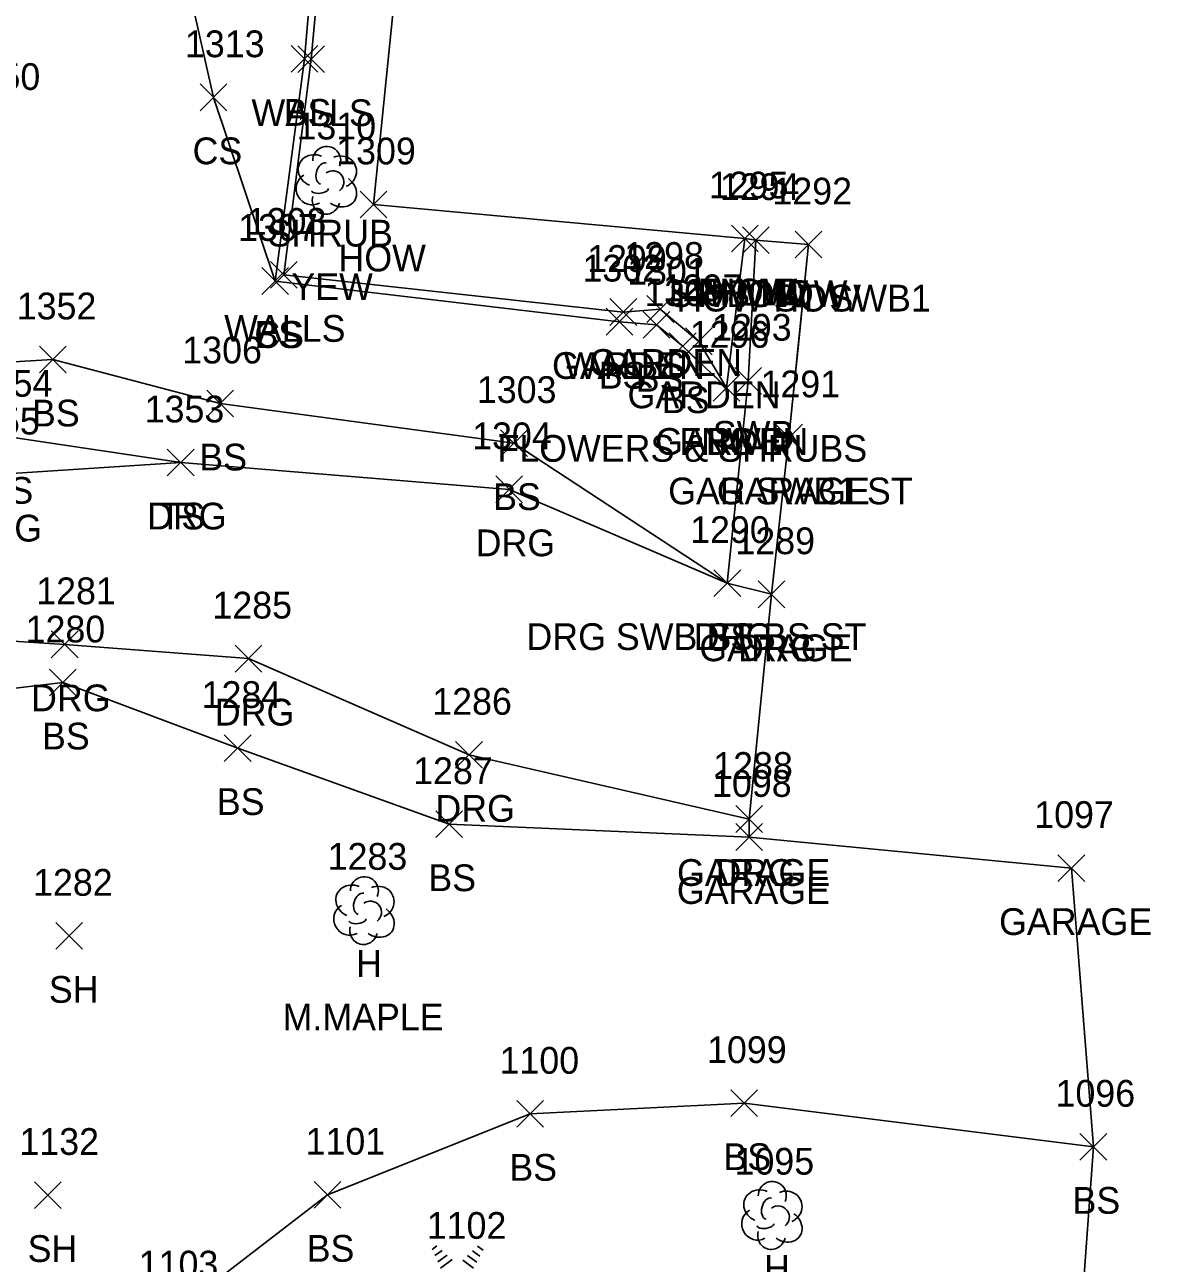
# Model space of a CAD drawing. Extents: x 1459992 to 1461532, y 647785 to 648535.
# Drawn here: x 1461426.2 to 1461510.8, y 648040.8 to 648133.4 of the extents above; entities that cross this region are included whole.
import ezdxf

# ---------------------------------------------------------------- set-up
doc = ezdxf.new("R2010")
doc.units = 0
for name, color, linetype in [('L_A', 7, 'Continuous'), ('L_C', 7, 'Continuous'), ('L_I', 7, 'Continuous'), ('L_TIC', 7, 'Continuous'), ('LAPB', 7, 'Continuous'), ('LBC', 7, 'Continuous'), ('LELB', 7, 'Continuous'), ('LFNC', 7, 'Continuous'), ('LSH', 7, 'Continuous'), ('LSOGP', 7, 'Continuous'), ('LTC', 7, 'Continuous'), ('LTD', 7, 'Continuous'), ('LWS', 7, 'Continuous'), ('R_A', 7, 'Continuous'), ('R_I', 7, 'Continuous'), ('R_TIC', 7, 'Continuous'), ('RDG', 7, 'Continuous'), ('RSW', 7, 'Continuous')]:
    doc.layers.add(name, color=color, linetype=linetype)

msp = doc.modelspace()

# ---------------------------------------------------------------- linework, layer by layer
at = {"layer": 'L_TIC'}
for points in [[(1461446.088, 648129.848), (1461448.088, 648131.848)], [(1461448.088, 648129.848), (1461446.088, 648131.848)], [(1461446.586, 648129.826), (1461448.586, 648131.826)], [(1461448.586, 648129.826), (1461446.586, 648131.826)], [(1461439.283, 648126.978), (1461441.283, 648128.978)], [(1461441.283, 648126.978), (1461439.283, 648128.978)], [(1461451.246, 648118.97), (1461453.246, 648120.97)], [(1461453.246, 648118.97), (1461451.246, 648120.97)], [(1461479.013, 648116.425), (1461481.013, 648118.425)], [(1461481.013, 648116.425), (1461479.013, 648118.425)], [(1461479.013, 648116.425), (1461481.013, 648118.425)], [(1461481.013, 648116.425), (1461479.013, 648118.425)], [(1461479.834, 648116.302), (1461481.834, 648118.302)], [(1461481.834, 648116.302), (1461479.834, 648118.302)], [(1461483.766, 648115.971), (1461485.766, 648117.971)], [(1461485.766, 648115.971), (1461483.766, 648117.971)], [(1461443.9, 648113.251), (1461445.9, 648115.251)], [(1461445.9, 648113.251), (1461443.9, 648115.251)], [(1461443.9, 648113.251), (1461445.9, 648115.251)], [(1461445.9, 648113.251), (1461443.9, 648115.251)], [(1461444.548, 648113.706), (1461446.548, 648115.706)], [(1461446.548, 648113.706), (1461444.548, 648115.706)], [(1461469.924, 648110.932), (1461471.924, 648112.932)], [(1461471.924, 648110.932), (1461469.924, 648112.932)], [(1461469.924, 648110.932), (1461471.924, 648112.932)], [(1461471.924, 648110.932), (1461469.924, 648112.932)], [(1461472.691, 648111.158), (1461474.691, 648113.158)], [(1461474.691, 648111.158), (1461472.691, 648113.158)], [(1461469.642, 648110.211), (1461471.642, 648112.211)], [(1461471.642, 648110.211), (1461469.642, 648112.211)], [(1461472.414, 648109.979), (1461474.414, 648111.979)], [(1461474.414, 648109.979), (1461472.414, 648111.979)], [(1461475.57, 648108.742), (1461477.57, 648110.742)], [(1461477.57, 648108.742), (1461475.57, 648110.742)], [(1461474.363, 648108.376), (1461476.363, 648110.376)], [(1461476.363, 648108.376), (1461474.363, 648110.376)], [(1461427.276, 648107.381), (1461429.276, 648109.381)], [(1461429.276, 648107.381), (1461427.276, 648109.381)], [(1461477.642, 648105.259), (1461479.642, 648107.259)], [(1461479.642, 648105.259), (1461477.642, 648107.259)], [(1461477.642, 648105.259), (1461479.642, 648107.259)], [(1461479.642, 648105.259), (1461477.642, 648107.259)], [(1461477.642, 648105.259), (1461479.642, 648107.259)], [(1461479.642, 648105.259), (1461477.642, 648107.259)], [(1461439.785, 648104.09), (1461441.785, 648106.09)], [(1461441.785, 648104.09), (1461439.785, 648106.09)], [(1461461.751, 648101.134), (1461463.751, 648103.134)], [(1461463.751, 648101.134), (1461461.751, 648103.134)], [(1461482.309, 648101.559), (1461484.309, 648103.559)], [(1461484.309, 648101.559), (1461482.309, 648103.559)], [(1461436.839, 648099.682), (1461438.839, 648101.682)], [(1461438.839, 648099.682), (1461436.839, 648101.682)], [(1461477.701, 648090.669), (1461479.701, 648092.669)], [(1461479.701, 648090.669), (1461477.701, 648092.669)], [(1461481.007, 648089.834), (1461483.007, 648091.834)], [(1461483.007, 648089.834), (1461481.007, 648091.834)], [(1461428.026, 648083.238), (1461430.026, 648085.238)], [(1461430.026, 648083.238), (1461428.026, 648085.238)], [(1461441.097, 648078.34), (1461443.097, 648080.34)], [(1461443.097, 648078.34), (1461441.097, 648080.34)], [(1461456.906, 648072.647), (1461458.906, 648074.647)], [(1461458.906, 648072.647), (1461456.906, 648074.647)], [(1461479.341, 648073.039), (1461481.341, 648075.039)], [(1461481.341, 648073.039), (1461479.341, 648075.039)], [(1461479.33, 648071.695), (1461481.33, 648073.695)], [(1461481.33, 648071.695), (1461479.33, 648073.695)], [(1461503.417, 648069.371), (1461505.417, 648071.371)], [(1461505.417, 648069.371), (1461503.417, 648071.371)], [(1461428.496, 648064.303), (1461430.496, 648066.303)], [(1461430.496, 648064.303), (1461428.496, 648066.303)], [(1461478.966, 648051.799), (1461480.966, 648053.799)], [(1461480.966, 648051.799), (1461478.966, 648053.799)], [(1461462.964, 648051.002), (1461464.964, 648053.002)], [(1461464.964, 648051.002), (1461462.964, 648053.002)], [(1461505.064, 648048.536), (1461507.064, 648050.536)], [(1461507.064, 648048.536), (1461505.064, 648050.536)], [(1461426.909, 648044.934), (1461428.909, 648046.934)], [(1461428.909, 648044.934), (1461426.909, 648046.934)], [(1461447.813, 648044.95), (1461449.813, 648046.95)], [(1461449.813, 648044.95), (1461447.813, 648046.95)]]:
    msp.add_lwpolyline(points, dxfattribs=at)
at = {"layer": 'LAPB'}
msp.add_lwpolyline([(1461478.642, 648106.259), (1461476.57, 648109.742), (1461473.691, 648112.158), (1461470.924, 648111.932)], dxfattribs=at)
at = {"layer": 'LBC'}
for points in [[(1461484.766, 648116.971), (1461480.834, 648117.302), (1461480.013, 648117.425), (1461452.246, 648119.97), (1461454.719, 648144.346), (1461455.253, 648148.958), (1461456.188, 648156.006), (1461467.518, 648153.848), (1461468.549, 648154.495), (1461472.343, 648154.285), (1461472.694, 648154.145), (1461482.334, 648153.047), (1461488.134, 648152.667), (1461488.857, 648152.617), (1461489.981, 648152.534), (1461490.817, 648159.203), (1461493.888, 648169.678), (1461510.763, 648168.099)], [(1461504.417, 648070.371), (1461480.33, 648072.695), (1461480.341, 648074.039), (1461482.007, 648090.834), (1461483.309, 648102.559)]]:
    msp.add_lwpolyline(points, dxfattribs=at)
at = {"layer": 'LELB'}
for points in [[(1461437.839, 648100.682), (1461424.99, 648102.601), (1461410.253, 648104.75), (1461403.249, 648108.099), (1461397.824, 648111.829), (1461393.938, 648122.147), (1461389.604, 648129.591), (1461386.85, 648142.876), (1461378.611, 648152.668), (1461368.623, 648163.532), (1461366.902, 648163.443), (1461362.607, 648163.899), (1461362.17, 648163.299)], [(1461478.642, 648106.259), (1461475.363, 648109.376), (1461473.414, 648110.979), (1461470.642, 648111.211), (1461444.9, 648114.251), (1461447.088, 648130.848), (1461448.323, 648145.003)], [(1461444.9, 648114.251), (1461440.283, 648127.978), (1461437.277, 648141.38), (1461441.027, 648143.03)], [(1461478.701, 648091.669), (1461462.751, 648102.134), (1461440.785, 648105.09), (1461428.276, 648108.381), (1461412.42, 648107.446), (1461407.924, 648110.162)], [(1461409.621, 648042.868), (1461407.442, 648074.421), (1461411.254, 648075.168), (1461411.242, 648082.118), (1461429.026, 648084.238), (1461442.097, 648079.34), (1461457.906, 648073.647)], [(1461457.906, 648073.647), (1461480.33, 648072.695)], [(1461506.064, 648049.536), (1461479.966, 648052.799), (1461463.964, 648052.002), (1461448.813, 648045.95), (1461436.904, 648036.773), (1461445.761, 648020.391), (1461448.916, 648009.123), (1461443.789, 647990.405)]]:
    msp.add_lwpolyline(points, dxfattribs=at)
at = {"layer": 'LFNC'}
msp.add_lwpolyline([(1461480.013, 648117.425), (1461478.642, 648106.259)], dxfattribs=at)
at = {"layer": 'LSH'}
msp.add_line((1461448.709, 648121.828), (1461448.709, 648121.828), dxfattribs=at)
msp.add_line((1461448.709, 648121.828), (1461448.709, 648121.828), dxfattribs=at)
msp.add_arc((1461448.756, 648123.262), 1.047, 335.52715, 180.95627, dxfattribs=at)
for centre, major_axis, ratio, start_param, end_param in [((1461447.917, 648122.495), (1.21, -0.512), 0.895232, 1.570796, 4.712389), ((1461449.751, 648122.412), (-1.141, -0.483), 0.949671, 1.570796, 4.712389), ((1461448.501, 648122.286), (-0.208, -0.792), 0.645439, 3.141593, 6.283185), ((1461449.209, 648121.662), (-0.5, 0.667), 0.989748, 3.141593, 6.283185), ((1461447.626, 648121.12), (0.584, -1.042), 0.959034, 3.141593, 6.283185), ((1461449.709, 648120.995), (-1.09, 0.792), 0.841452, 1.570796, 4.712389), ((1461448.251, 648121.078), (-0.625, -0.083), 0.423636, 0, 3.141593), ((1461448.709, 648120.328), (0.265, 1.061), 0.942809, 1.570796, 4.712389)]:
    msp.add_ellipse(centre, major_axis=major_axis, ratio=ratio, start_param=start_param, end_param=end_param, dxfattribs=at)
at = {"layer": 'LSOGP'}
msp.add_lwpolyline([(1461503.631, 648016.057), (1461506.064, 648049.536), (1461504.417, 648070.371), (1461480.33, 648072.695), (1461480.341, 648074.039), (1461482.007, 648090.834), (1461483.309, 648102.559), (1461484.038, 648109.765), (1461484.766, 648116.971), (1461480.834, 648117.302), (1461480.013, 648117.425), (1461452.246, 648119.97), (1461454.719, 648144.346)], dxfattribs=at)
at = {"layer": 'LTC'}
for p, q in [((1461456.634, 648041.87), (1461456.988, 648042.128)), ((1461460.032, 648042.111), (1461460.451, 648041.806)), ((1461456.843, 648041.405), (1461457.372, 648041.789)), ((1461457.053, 648040.939), (1461457.757, 648041.45)), ((1461457.262, 648040.473), (1461458.141, 648041.111)), ((1461458.919, 648041.066), (1461459.728, 648040.477)), ((1461459.29, 648041.414), (1461459.969, 648040.92)), ((1461459.661, 648041.762), (1461460.21, 648041.363))]:
    msp.add_line(p, q, dxfattribs=at)
at = {"layer": 'LTD'}
for p, q in [((1461451.519, 648067.243), (1461451.519, 648067.243)), ((1461451.519, 648067.243), (1461451.519, 648067.243)), ((1461482.013, 648044.459), (1461482.013, 648044.459)), ((1461482.013, 648044.459), (1461482.013, 648044.459))]:
    msp.add_line(p, q, dxfattribs=at)
for centre in [(1461451.566, 648068.677), (1461482.06, 648045.893)]:
    msp.add_arc(centre, 1.047, 335.52715, 180.95627, dxfattribs=at)
for centre, major_axis, ratio, start_param, end_param in [((1461450.727, 648067.909), (1.21, -0.512), 0.895232, 1.570796, 4.712389), ((1461452.561, 648067.826), (-1.141, -0.483), 0.949671, 1.570796, 4.712389), ((1461451.311, 648067.701), (-0.208, -0.792), 0.645439, 3.141593, 6.283185), ((1461452.019, 648067.076), (-0.5, 0.667), 0.989748, 3.141593, 6.283185), ((1461450.436, 648066.534), (0.584, -1.042), 0.959034, 3.141593, 6.283185), ((1461452.519, 648066.409), (-1.09, 0.792), 0.841452, 1.570796, 4.712389), ((1461451.061, 648066.493), (-0.625, -0.083), 0.423636, 0, 3.141593), ((1461451.519, 648065.743), (0.265, 1.061), 0.942809, 1.570796, 4.712389), ((1461481.221, 648045.125), (1.21, -0.512), 0.895232, 1.570796, 4.712389), ((1461481.805, 648044.917), (-0.208, -0.792), 0.645439, 3.141593, 6.283185), ((1461483.055, 648045.042), (-1.141, -0.483), 0.949671, 1.570796, 4.712389), ((1461480.93, 648043.75), (0.584, -1.042), 0.959034, 3.141593, 6.283185), ((1461482.513, 648044.292), (-0.5, 0.667), 0.989748, 3.141593, 6.283185), ((1461483.013, 648043.625), (-1.09, 0.792), 0.841452, 1.570796, 4.712389), ((1461482.013, 648042.959), (0.265, 1.061), 0.942809, 1.570796, 4.712389), ((1461481.555, 648043.709), (-0.625, -0.083), 0.423636, 0, 3.141593)]:
    msp.add_ellipse(centre, major_axis=major_axis, ratio=ratio, start_param=start_param, end_param=end_param, dxfattribs=at)
at = {"layer": 'LWS'}
msp.add_lwpolyline([(1461470.924, 648111.932), (1461445.548, 648114.706), (1461447.586, 648130.826), (1461448.863, 648144.723), (1461449.767, 648144.952)], dxfattribs=at)
at = {"layer": 'R_TIC'}
for points in [[(1461479.834, 648116.302), (1461481.834, 648118.302)], [(1461481.834, 648116.302), (1461479.834, 648118.302)], [(1461483.766, 648115.971), (1461485.766, 648117.971)], [(1461485.766, 648115.971), (1461483.766, 648117.971)], [(1461479.251, 648105.791), (1461481.251, 648107.791)], [(1461481.251, 648105.791), (1461479.251, 648107.791)], [(1461482.309, 648101.559), (1461484.309, 648103.559)], [(1461484.309, 648101.559), (1461482.309, 648103.559)], [(1461436.839, 648099.682), (1461438.839, 648101.682)], [(1461438.839, 648099.682), (1461436.839, 648101.682)], [(1461461.397, 648097.679), (1461463.397, 648099.679)], [(1461463.397, 648097.679), (1461461.397, 648099.679)], [(1461477.701, 648090.669), (1461479.701, 648092.669)], [(1461479.701, 648090.669), (1461477.701, 648092.669)], [(1461477.701, 648090.669), (1461479.701, 648092.669)], [(1461479.701, 648090.669), (1461477.701, 648092.669)], [(1461481.007, 648089.834), (1461483.007, 648091.834)], [(1461483.007, 648089.834), (1461481.007, 648091.834)], [(1461428.165, 648086.093), (1461430.165, 648088.093)], [(1461430.165, 648086.093), (1461428.165, 648088.093)], [(1461441.904, 648085.026), (1461443.904, 648087.026)], [(1461443.904, 648085.026), (1461441.904, 648087.026)], [(1461458.391, 648077.833), (1461460.391, 648079.833)], [(1461460.391, 648077.833), (1461458.391, 648079.833)], [(1461479.341, 648073.039), (1461481.341, 648075.039)], [(1461481.341, 648073.039), (1461479.341, 648075.039)]]:
    msp.add_lwpolyline(points, dxfattribs=at)
at = {"layer": 'RDG'}
for points in [[(1461482.007, 648090.834), (1461478.701, 648091.669), (1461462.397, 648098.679), (1461437.839, 648100.682), (1461424.043, 648099.78), (1461408.345, 648102.018), (1461401.638, 648105.031), (1461395.979, 648109.613)], [(1461402.282, 648079.787), (1461405.045, 648083.594), (1461411.011, 648088.257), (1461429.165, 648087.093), (1461442.904, 648086.026), (1461459.391, 648078.833), (1461480.341, 648074.039)]]:
    msp.add_lwpolyline(points, dxfattribs=at)
at = {"layer": 'RSW'}
for points in [[(1461478.701, 648091.669), (1461480.251, 648106.791), (1461480.834, 648117.302)], [(1461483.309, 648102.559), (1461484.766, 648116.971)]]:
    msp.add_lwpolyline(points, dxfattribs=at)

# ---------------------------------------------------------------- texts
at = {"layer": 'L_A'}
for s, p in [('WALLS', (1461443.129, 648125.826)), ('BS', (1461445.529, 648125.848)), ('CS', (1461438.724, 648122.978)), ('SHRUB', (1461444.339, 648116.828)), ('HOW', (1461449.632, 648114.97)), ('FNWD', (1461476.478, 648112.425)), ('HOW', (1461477.399, 648112.425)), ('HOW', (1461478.22, 648112.302)), ('HOW', (1461482.152, 648111.971)), ('WALLS', (1461441.091, 648109.706)), ('CS', (1461443.341, 648109.251)), ('BS', (1461443.341, 648109.251)), ('GARDEN', (1461465.594, 648106.932)), ('WALLS', (1461466.468, 648106.932)), ('GARDEN', (1461468.361, 648107.158)), ('BS', (1461469.083, 648106.211)), ('BS', (1461471.855, 648105.979)), ('GARDEN', (1461471.239, 648104.742)), ('BS', (1461473.804, 648104.376)), ('BS', (1461426.717, 648103.381)), ('GARDEN', (1461473.311, 648101.259)), ('FNWD', (1461475.106, 648101.259)), ('BS', (1461477.083, 648101.259)), ('BS', (1461439.226, 648100.09)), ('TS', (1461423.399, 648097.601)), ('GARAGE', (1461477.908, 648097.559)), ('BS', (1461461.192, 648097.134)), ('TS', (1461436.249, 648095.682)), ('BS', (1461477.142, 648086.669)), ('GARAGE', (1461476.606, 648085.834)), ('BS', (1461427.467, 648079.238)), ('BS', (1461440.538, 648074.34)), ('GARAGE', (1461474.94, 648069.039)), ('BS', (1461456.347, 648068.647)), ('GARAGE', (1461474.929, 648067.695)), ('GARAGE', (1461499.015, 648065.371)), ('H', (1461450.952, 648062.243)), ('SH', (1461427.984, 648060.303)), ('BS', (1461478.407, 648047.799)), ('BS', (1461462.405, 648047.002)), ('BS', (1461504.505, 648044.536)), ('SH', (1461426.397, 648040.934)), ('BS', (1461447.254, 648040.95)), ('H', (1461481.446, 648039.459))]:
    msp.add_text(s, height=2, dxfattribs=at).set_placement(p)
at = {"layer": 'L_C'}
for s, p in [('YEW', (1461446.111, 648112.828)), ('FLOWERS & SHRUBS', (1461461.515, 648100.742)), ('M.MAPLE', (1461445.456, 648058.243))]:
    msp.add_text(s, height=2, dxfattribs=at).set_placement(p)
at = {"layer": 'L_I'}
for s, p in [('1313', (1461438.157, 648130.978)), ('1350', (1461421.393, 648128.53)), ('1310', (1461446.497, 648124.828)), ('1309', (1461449.466, 648122.97)), ('1295', (1461477.32, 648120.425)), ('1295', (1461477.32, 648120.425)), ('1294', (1461478.141, 648120.302)), ('1292', (1461482.073, 648119.971)), ('1307', (1461442.129, 648117.251)), ('1307', (1461442.129, 648117.251)), ('1308', (1461442.776, 648117.706)), ('1298', (1461470.998, 648115.158)), ('1302', (1461467.871, 648114.211)), ('1299', (1461468.224, 648114.932)), ('1299', (1461468.224, 648114.932)), ('1301', (1461471.21, 648113.979)), ('1300', (1461472.505, 648112.376)), ('1297', (1461473.877, 648112.742)), ('1352', (1461425.583, 648111.381)), ('1296', (1461475.894, 648109.259)), ('1296', (1461475.894, 648109.259)), ('1296', (1461475.894, 648109.259)), ('1306', (1461437.958, 648108.09)), ('1354', (1461422.297, 648105.601)), ('1303', (1461459.98, 648105.134)), ('1291', (1461481.183, 648105.559)), ('1353', (1461435.146, 648103.682)), ('1290', (1461475.921, 648094.669)), ('1289', (1461479.307, 648093.834)), ('1280', (1461426.247, 648087.238)), ('1284', (1461439.404, 648082.34)), ('1288', (1461477.648, 648077.039)), ('1287', (1461455.213, 648076.647)), ('1098', (1461477.559, 648075.695)), ('1097', (1461501.645, 648073.371)), ('1283', (1461448.826, 648070.243)), ('1282', (1461426.803, 648068.303)), ('1099', (1461477.187, 648055.799)), ('1100', (1461461.673, 648055.002)), ('1096', (1461503.237, 648052.536)), ('1132', (1461425.783, 648048.934)), ('1101', (1461447.175, 648048.95)), ('1095', (1461479.242, 648047.459)), ('1102', (1461456.234, 648042.662)), ('1103', (1461434.7, 648039.773))]:
    msp.add_text(s, height=2, dxfattribs=at).set_placement(p)
at = {"layer": 'R_A'}
for s, p in [('SWB HOW', (1461474.315, 648112.302)), ('HOW ST SWB1', (1461474.892, 648111.971)), ('SWB', (1461477.613, 648101.791)), ('GAR SWB1 ST', (1461474.278, 648097.559)), ('DRG', (1461435.327, 648095.682)), ('DRG', (1461421.532, 648094.78)), ('DRG', (1461459.886, 648093.679)), ('DRG SWB ST BS ST', (1461463.685, 648086.669)), ('DRG', (1461476.189, 648086.669)), ('DRG', (1461479.496, 648085.834)), ('DRG', (1461426.653, 648082.093)), ('DRG', (1461440.392, 648081.026)), ('DRG', (1461456.879, 648073.833)), ('DRG', (1461477.83, 648069.039))]:
    msp.add_text(s, height=2, dxfattribs=at).set_placement(p)
at = {"layer": 'R_I'}
for s, p in [('1294', (1461478.141, 648120.302)), ('1292', (1461482.073, 648119.971)), ('1293', (1461477.558, 648109.791)), ('1291', (1461481.183, 648105.559)), ('1353', (1461435.146, 648103.682)), ('1355', (1461421.35, 648102.78)), ('1304', (1461459.626, 648101.679)), ('1290', (1461475.921, 648094.669)), ('1290', (1461475.921, 648094.669)), ('1289', (1461479.307, 648093.834)), ('1281', (1461427.039, 648090.093)), ('1285', (1461440.211, 648089.026)), ('1286', (1461456.643, 648081.833)), ('1288', (1461477.648, 648077.039))]:
    msp.add_text(s, height=2, dxfattribs=at).set_placement(p)

doc.saveas('drawing.dxf')
